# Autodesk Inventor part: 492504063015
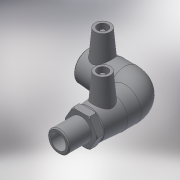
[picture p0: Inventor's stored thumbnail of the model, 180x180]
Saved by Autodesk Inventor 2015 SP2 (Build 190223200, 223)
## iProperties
Created: 2017-06
Part Number: 492504063015
Material: Generic
Description: PLASSON 90° ELBOW MALE TRANSITION 63-1.1/2"
Document SubType Name: Modeling
Designer: KIM
Mass: 488.328 g
Surface Area: 954.336 cm^2
Volume: 488.328 cm^3
Density: 1 g/cm^3
Appearance: Default
Author: KIM
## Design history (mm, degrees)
derived "492504.ipt"
feature "Solid1::492504.ipt"
tag "TaggingFeature1"
body "Solid1"
other parameters: "d2" = 82, "d4" = 43.66667, "d5" = 73.8, "d8" = 168 deg, "d10" = 22.8, "d11" = 7.6, "d29" = 59, "d30" = 15, "d31" = 72.05, "d34" = 5 deg, "d41" = 4, "d42" = 14, "d43" = 0, "d49" = 63, "d50" = 53.55, "d51" = 22.8, "d52" = 57, "d54" = 90 deg, "d57" = 63, "d58" = 57, "d59" = 0, "d61" = 90 deg, "d86" = 3, "d87" = 0, "d93" = 0.1, "d94" = 9, "d95" = 47.803, "d96" = 33.4621, "d97" = 48, "d98" = 36, "d99" = 82, "d100" = 32.4, "d102" = 2.52, "d106" = 0, "d_" = 63, "L_" = 167, "L_1" = 57, "D_" = 48, "A_" = 59, "d_2" = 12, "L_2" = 36, "D_1" = 82, "R_" = 47.803
